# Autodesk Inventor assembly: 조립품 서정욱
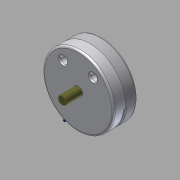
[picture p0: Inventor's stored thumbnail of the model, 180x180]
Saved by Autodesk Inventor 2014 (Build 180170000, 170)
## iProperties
Created: 2015-05
Part Number: 조립품 서정욱
Document SubType Name: Assembly
Designer: USER
Author: USER
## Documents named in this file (10)
- C:\Users\USER\Desktop\Inventor2급-서정욱\조립품 서정욱.iam
- C:\Users\USER\Desktop\Inventor2급-서정욱\서정욱.ipt
- C:\Users\USER\Desktop\Inventor2급-서정욱\20150513-2급공용부품\M 10 x 35.ipt
- C:\Users\USER\Desktop\Inventor2급-서정욱\20150513-2급공용부품\덮개.ipt
- C:\Users\USER\Desktop\Inventor2급-서정욱\20150513-2급공용부품\멈춤링.ipt
- C:\Users\USER\Desktop\Inventor2급-서정욱\20150513-2급공용부품\베어링62_22.ipt
- C:\Users\USER\Desktop\Inventor2급-서정욱\20150513-2급공용부품\슬라이더.ipt
- C:\Users\USER\Desktop\Inventor2급-서정욱\20150513-2급공용부품\슬라이더2.ipt
- C:\Users\USER\Desktop\Inventor2급-서정욱\20150513-2급공용부품\축.ipt
- C:\Users\USER\Desktop\Inventor2급-서정욱\20150513-2급공용부품\평행핀.ipt
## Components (2 placed, 1 different names)
1. M 10 x 35:1
2. M 10 x 35:2
